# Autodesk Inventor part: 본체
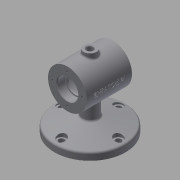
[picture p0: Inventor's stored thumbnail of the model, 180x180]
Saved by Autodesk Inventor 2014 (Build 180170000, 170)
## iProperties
Created: 2018-12
Part Number: 본체
Material: Generic
Document SubType Name: Modeling
Designer: kh
Density: 1 g/cm^3
Appearance: Default
Author: kh
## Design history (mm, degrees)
sketch "Sketch1"
  geometry: L1 (0, 0)-(70, 0); L2 (70, 0)-(70, 30); L3 (70, 30)-(0, 30); L4 (0, 30)-(0, 0)
  constraints: 8 end point, 2 parallel, 1 horizontal, 1 perpendicular
  dimensions: "d0" = 70 distance of L2.end L3.end; "d1" = 60 diameter of L3 L1
revolve "Revolution1" sketch "Sketch1" stored, may be unused: angle "d2" = 90 deg
sketch "Sketch2"
  geometry: L1 (0, -30)-(0, 30) reference; L2 (70, -30)-(70, 30) reference; L3 (0, 30)-(70, 30) reference; L4 (0, -30)-(70, -30) reference; L5 (0, 0)-(70, 0); L6 (0, 17)-(1, 16); L7 (1, 16)-(11.7, 16); L8 (12, 15.7)-(12, 14); L9 (12, 14)-(15, 14); L10 (15, 14)-(15, 22); L11 (18, 25)-(52, 25); L12 (55, 22)-(55, 14); L13 (55, 14)-(58, 14); L14 (58, 14)-(58, 16); L15 (58, 16)-(69, 16); L16 (69, 16)-(70, 17); L17 (0, 17)-(0, 0); L18 (70, 17)-(70, 0); A1 r 3 centre (18, 22) between (18, 25) and (15, 22); A2 r 3 centre (52, 22) between (55, 22) and (52, 25); A3 r 0.3 centre (11.7, 15.7) between (12, 15.7) and (11.7, 16); 2 further points
  constraints: 28 end point, 10 perpendicular, 6 point on circle, 6 point on line, 6 tangent, 3 centre point, 2 collinear, 1 equal radius, 1 midpoint, 1 parallel
  dimensions: "d4" = 50 diameter of L11 L5; "d5" = 28 diameter of L13 L5; "d6" = 28 diameter of L9 L5; "d7" = 32 diameter of L7 L5; "d8" = 32 diameter of L15 L5; "d9" = 1 horizontal distance of L6.start L6.end; "d10" = 1 horizontal distance of L6.start L6.end; "d11" = 1 horizontal distance of L15.end L16.end; "d12" = 12 distance from line of L8 L6.start; "d13" = 12 distance from line of L16.end L14; "d15" = 40 distance of point (15, 25) point (55, 25); "d16" = 3 radius of A1; "d17" = 0.3 radius of A3
revolve "Revolution2" sketch "Sketch2" stored, may be unused: angle "d18" = 90 deg
sketch "Sketch3"
  geometry: L1 (-23, 0)-(23, 0); L2 (0, 23)-(0, -23); C1 r 30 at (0, 0) reference; A1 r 23 centre (0, 0) between (-23, 0) and (23, 0); 3 further points
  constraints: 4 end point, 4 point on circle, 2 coincident, 2 midpoint, 1 centre point, 1 horizontal, 1 perpendicular
  dimensions: "d19" = 46 diameter of A1
hole "Hole1" sketch "Sketch3" at (0, 23) diameter "d20" = 3.242; stored, may be unused: countersink angle "d24" = 90 deg, drill point angle "d26" = 118 deg; dims "d21" = 8, "d22" = 4, "d23" = 2, "d25" = 10
pattern_circular "Circular Pattern1" dims angle "d28" = 360 deg
workplane "Work Plane1"
mirror "Mirror1"
workplane "Work Plane2"
sketch "Sketch4"
  geometry: L1 (0, 30)-(0, -30) reference; L2 (0, -30)-(-70, -30) reference; L3 (-70, 30)-(-70, -30) reference; L4 (0, 30)-(-70, 30) reference; L5 (0, 0)-(-70, 0); L6 (-35, -30)-(-35, 30); C1 r 55 at (-35, 0)
  constraints: 4 end point, 4 midpoint, 1 centre point
  dimensions: "d31" = 110 diameter of C1
extrude "Extrusion1" join sketch "Sketch4" distance "d32" = 11; taper "d33" = 0 deg
sketch "Sketch5"
  geometry: L1 (20, -64)-(-90, -64) reference; L2 (-90, -75)-(-90, -64) reference; L3 (-90, -64)-(-35, -49.263); L4 (0, -30)-(-70, -30) reference; L5 (-35, -64)-(-35, -30); L6 (-35, -49.263)-(-35, -64); L7 (-90, -64)-(-35, -64); 1 further point
  constraints: 8 end point, 2 collinear, 2 midpoint, 1 point on line
  dimensions: "d34" = 75 deg angle of L3 L2
revolve "Revolution3" sketch "Sketch5" stored, may be unused: angle "d35" = 90 deg
sketch "Sketch7"
  geometry: L1 (-90, 0)-(20, 0); L2 (-35, 55)-(-35, -55); C1 r 12 at (-35, 0); A1 r 55 centre (-35, 0) between (-90, 0) and (-35, 55) reference; 2 further points
  constraints: 4 end point, 3 midpoint, 3 point on circle, 1 centre point, 1 coincident, 1 horizontal, 1 perpendicular
  dimensions: "d36" = 24 diameter of C1
extrude "Extrusion2" join sketch "Sketch7" stored distance "d37" = 11; taper "d38" = 0 deg
workplane "Work Plane3"
sketch "Sketch8"
  geometry: L1 (0, -30)-(0, 30) reference; L2 (70, -30)-(70, 30) reference; L3 (0, 0)-(70, 0); L4 (0, 30)-(70, 30) reference; L5 (0, -30)-(70, -30) reference; L6 (35, 30)-(35, -30); C1 r 10 at (35, 0)
  constraints: 4 end point, 4 midpoint, 1 centre point
  dimensions: "d40" = 20 diameter of C1
extrude "Extrusion3" join sketch "Sketch8" stored distance "d41" = 11; taper "d42" = 0 deg
hole "Hole2" diameter "d45" = 10; stored, may be unused: countersink angle "d49" = 90 deg, drill point angle "d51" = 118 deg; dims "d46" = 8, "d47" = 4, "d48" = 2, "d50" = 10, "d52" = 10, "d53" = 10
sketch "Sketch11"
  geometry: L1 (-44, 0)-(44, 0); L2 (0, 44)-(0, -44); C1 r 55 at (0, 0) reference; C2 r 4.5 at (0, 44); C3 r 4.5 at (44, 0); C4 r 4.5 at (0, -44); C5 r 4.5 at (-44, 0); A1 r 44 centre (0, 0) between (-44, 0) and (44, 0); 1 further point
  constraints: 5 centre point, 5 coincident, 4 end point, 4 point on circle, 2 midpoint, 1 horizontal, 1 perpendicular
  dimensions: "d57" = 88 diameter of A1; "d82" = 9 diameter of C2; "d83" = 9 diameter of C3; "d84" = 9 diameter of C4; "d85" = 9 diameter of C5
workplane "Work Plane5"
workplane "Work Plane6"
sketch "Sketch13"
  geometry: L1 (0, -30)-(0, 30) reference; L2 (0, 30)-(70, 30) reference; L3 (10.113, 3.602)-(59.887, 3.602); L4 (59.887, 3.602)-(59.887, -3.602); L5 (59.887, -3.602)-(10.113, -3.602); L6 (10.113, -3.602)-(10.113, 3.602); L7 (10.113, 0)-(59.887, 0); L8 (35, 3.602)-(35, -3.602); 1 further point
  constraints: 4 end point, 4 midpoint, 2 other
  dimensions: "d74" = 35 distance between parallel lines of L8 L1; "d75" = 30 distance between parallel lines of L7 L2
emboss "Emboss1" sketch "Sketch13" dims "d0" = 70, "d1" = 60, "d76" = 0.5, "d77" = 0
fillet "Fillet1" dims "d78" = 3
chamfer "Chamfer1" distance "d79" = 1; stored, may be unused: second distance "d80" = 2, angle "d81" = 45 deg
sketch "Sketch14"
  geometry: 1 further point
sketch "Sketch15"
  geometry: L1 (-52.776, 0)-(52.776, 0); L2 (-44, 0)-(44, 0); L3 (0, 44)-(0, -44); C1 r 14.224 at (0, 0) reference; C2 r 7 at (0, 44); C3 r 7 at (44, 0); C4 r 7 at (0, -44); C5 r 7 at (-44, 0); A1 r 52.776 centre (0, 0) between (-52.776, 0) and (52.776, 0) reference; A2 r 44 centre (0, 0) between (-44, 0) and (44, 0); 3 further points
  constraints: 6 coincident, 6 end point, 6 point on circle, 5 centre point, 3 midpoint, 2 point on line, 1 horizontal, 1 perpendicular
  dimensions: "d88" = 88 diameter of A2; "d89" = 14 diameter of C2; "d90" = 14 diameter of C3; "d91" = 14 diameter of C4; "d92" = 14 diameter of C5
  node "Projected Loop6"
hole "Hole5" sketch "Sketch11" diameter "d95" = 9; stored, may be unused: countersink angle "d99" = 90 deg, drill point angle "d101" = 118 deg; dims "d96" = 6, "d97" = 4, "d98" = 2, "d100" = 8
hole "Hole6" sketch "Sketch15" diameter "d102" = 14; stored, may be unused: countersink angle "d106" = 90 deg, drill point angle "d108" = 118 deg; dims "d103" = 6, "d104" = 4, "d105" = 2, "d107" = 20
body "Solid1"
node "Projected Loop1"
other parameters: "d30" = -75, "d39" = 37, "d73" = -59.5
